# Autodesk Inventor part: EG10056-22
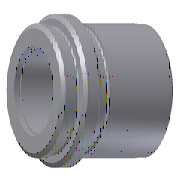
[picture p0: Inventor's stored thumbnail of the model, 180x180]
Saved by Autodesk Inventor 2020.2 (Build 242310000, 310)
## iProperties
Manager: www.cadconsulting.pl
Company: Fabian Stasiak CAD Consulting
Created: 2014-02
Part Number: EG10056-22
Material: DIN 1.7131
Description: Leader Pin Bushings
Document SubType Name: Modeling
Designer: F.Stasiak
Standard Revision: 1
Manufacturer: DME
Language: pl-PL
Size Designation: 56-22
Categories: <MemberInstance><Categories><Category DisplayName="Forma wtryskowa" InternalName="349578f2-f4d4-4954-8c09-8e99297a61c0" Mnemonic="MOLD"><Category DisplayName="K
Density: 7.85 g/cm^3
Appearance: Domyślna
Catalog Web Link: www.expertbooks.pl
IsCustomPart: 0
Author: F.Stasiak
Subject: Zbiór ćwiczeń. Autodesk Inventor 2020. Kurs Professional
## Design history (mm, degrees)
sketch "Sketch1"
  geometry: L1 (0, -16.8)-(0, 9.8) reference; L2 (0, 15)-(15, 15); L3 (15, 15)-(15, 7); L4 (15, 7)-(14.5, 7); L5 (14.5, 7)-(14.5, 6); L6 (14.5, 6)-(17.5, 6); L7 (17.5, 6)-(17.5, 0); L8 (17.5, 0)-(14.5, 0); L9 (14.5, 0)-(14.5, -1); L10 (14.5, -1)-(15, -1); L11 (15, -1)-(15, -49); L12 (15, -49)-(14.95, -49); L13 (14.95, -49)-(14.95, -50); L14 (14.95, -50)-(0, -50); L15 (0, 15)-(0, -50); 1 further point
  constraints: 28 end point, 7 parallel, 5 perpendicular, 2 collinear, 2 equal length, 2 point on line, 1 horizontal alignment
  dimensions: "d0" = 30 diameter of L11 L1 (= D); "d2" = 1 distance between parallel lines of L14 L12; "d27" = 29.9 diameter of L13 L1 (= D_Guide); "d4" = 35 diameter of L7 L1 (= D2); "d5" = 30 diameter of L3 L1 (= D1); "d6" = 6 distance between parallel lines of L8 L6 (= H_); "d7" = 56 distance between parallel lines of L14 L6 (= L); "d8" = 9 distance between parallel lines of L6 L2 (= L1); "d9" = 1 distance between parallel lines of L10 L8; "d10" = 0.5 distance between parallel lines of L11 L9
revolve "Revolution1" sketch "Sketch1" stored, may be unused: angle "d11" = 90 deg
sketch "Sketch2"
  geometry: L1 (-14.95, -50)-(14.95, -50) reference; L2 (11, -50)-(11, 6); L3 (11, 6)-(11, 6); L4 (11, 6)-(11, 71); L5 (0, -50)-(0, 71); L6 (0, 71)-(11, 71); L7 (11, -50)-(0, -50)
  constraints: 12 end point, 3 perpendicular, 2 collinear, 1 midpoint, 1 parallel, 1 point on line
  dimensions: "d12" = 22 diameter of L2 L5 (= d_); "d13" = 56 distance of L2.start L2.end (= l_); "d14" = 65 distance of L3.end L4.end (= L + L1); "d15" = 22 diameter of L4 L5 (= d3)
revolve "Revolution2" sketch "Sketch2" stored, may be unused: angle "d16" = 90 deg
chamfer "Chamfer1" distance "d17" = 0.5; stored, may be unused: second distance "d18" = 2, angle "d19" = 45 deg
fillet "Fillet1" dims "d20" = 0.3
fillet "Fillet2" dims "d21" = 0.8
body "Solid1"
other parameters: "d_" = 22 [user parameter; used in 1 equation term], "L" = 56 [user parameter; used in 2 equation terms], "D" = 30 [user parameter; used in 1 equation term], "D1" = 30 [user parameter; used in 1 equation term], "D2" = 35 [user parameter; used in 1 equation term], "H_" = 6 [user parameter; used in 1 equation term], "L1" = 9 [user parameter; used in 2 equation terms], "l_" = 56 [user parameter; used in 1 equation term], "d3" = 22 [user parameter; used in 1 equation term], "D_Guide" = 29.9 [user parameter; used in 1 equation term], "d22" = 0, "d23" = 0, "d24" = 0, "d25" = 0, "d26" = 0
